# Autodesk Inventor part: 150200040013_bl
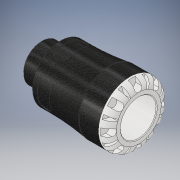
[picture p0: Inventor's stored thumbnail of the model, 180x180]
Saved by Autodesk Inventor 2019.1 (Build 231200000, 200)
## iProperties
Created: 2016-12
Part Number: 150200040013_bl
Material: PVC-Piping
Description: PLASSON G-PLASS Male Adaptor 40X 1 1/4''
Document SubType Name: Modeling
Designer: KIM
Mass: 61.7504 g
Surface Area: 140.097 cm^2
Volume: 44.1074 cm^3
Density: 1.4 g/cm^3
Appearance: Black Cast
Author: KIM
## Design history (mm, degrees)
derived "150200.ipt"
feature "Solid1::150200.ipt" dims "ScaleForDerivedMember" = 10
tag "TaggingFeature1"
body "Solid1"
other parameters: "d0" = 109 [user parameter], "d1" = 31.92 [user parameter], "d6" = 76 [user parameter], "d8" = 63 [user parameter], "d13" = 8 [user parameter], "d14" = 8 [user parameter], "d15" = 0 [user parameter], "d17" = 360 deg [user parameter], "d19" = 8 deg [user parameter], "d20" = 0.8 [user parameter], "d21" = 0.8 [user parameter], "d22" = 8 deg [user parameter], "d24" = 0 [user parameter], "d26" = 360 deg [user parameter], "d32" = 0.925 [user parameter], "d33" = 7 [user parameter], "d34" = 41.91 [user parameter], "d35" = 5 [user parameter], "d38" = 21 [user parameter], "d39" = 1.2573 [user parameter], "d42" = 14 [user parameter], "d43" = 9.2 [user parameter], "d45" = 15.68 [user parameter], "d46" = 0 [user parameter], "d59" = 360 deg [user parameter], "d61" = 11.9 [user parameter], "d62" = 0.8 [user parameter], "d64" = 0 [user parameter], "d65" = 0.7 [user parameter], "H_" = 109 [user parameter], "l_" = 76 [user parameter], "R_" = 41.91 [user parameter], "l_2" = 21 [user parameter]
